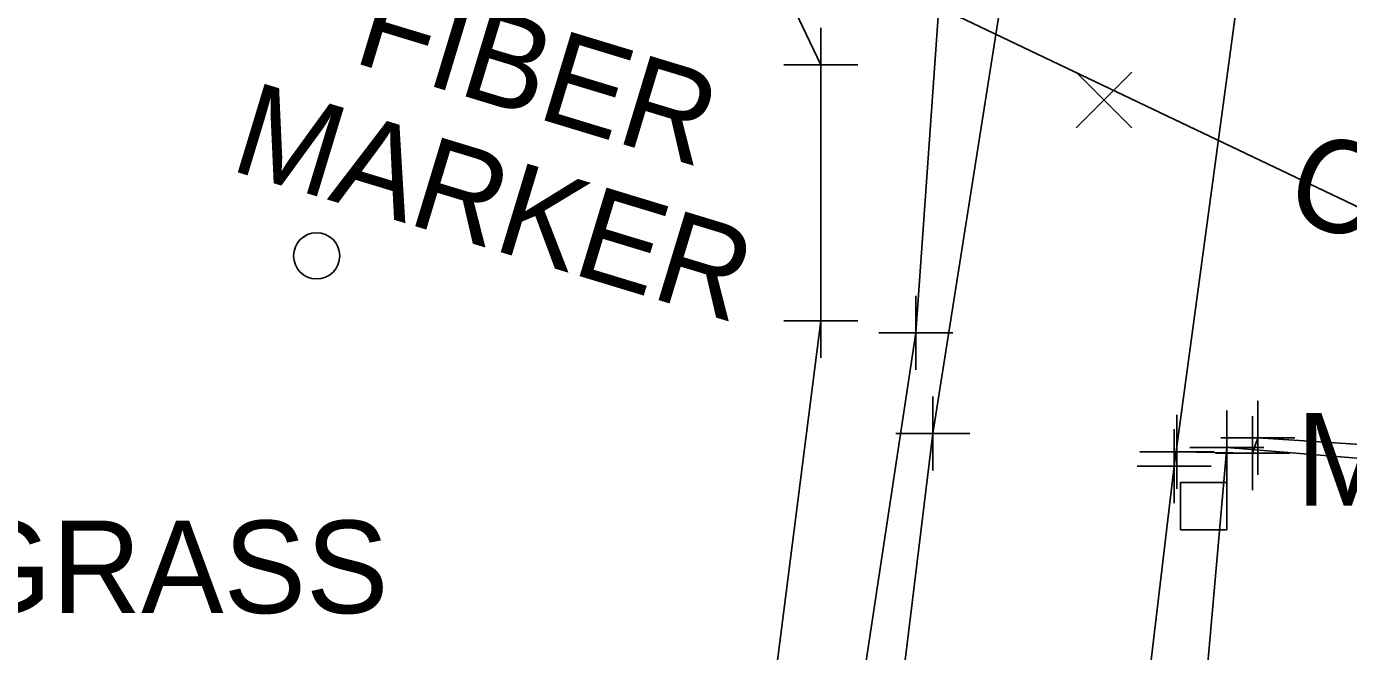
# Model space of a CAD drawing. Extents: x 0 to 1944463, y 0 to 420651.
# Drawn here: x 1942446.1 to 1942517.6, y 417841.3 to 417875.1 of the extents above; entities that cross this region are included whole.
import ezdxf

# ---------------------------------------------------------------- set-up
doc = ezdxf.new("R2010")
doc.units = 0
for name, color, linetype in [('SUR - DTM - Breaklines', 7, 'Continuous'), ('SUR - DTM - Breaklines - Points - Locators', 7, 'Continuous'), ('SUR - DTM - Spot Points - Locators', 7, 'Continuous'), ('SUR - NON-TRAN - Buildings', 7, 'Continuous'), ('SUR - NON-TRAN - Buildings - Points - Locators', 7, 'Continuous'), ('SUR - NON-TRAN - Features', 7, 'Continuous'), ('SUR - PROPERTY - Property Lines', 7, 'Continuous'), ('SUR - TRAN - Features', 7, 'Continuous'), ('SUR - TRAN - Features - Points - Locators', 7, 'Continuous'), ('SUR - TRAN - Features Text', 7, 'Continuous'), ('SUR - TRAN - Roads', 7, 'Continuous'), ('SUR - UTL - Fiber Optic Cable (Underground) Text', 7, 'Continuous'), ('SUR - UTL - Low Wire Crossings', 7, 'Continuous'), ('SUR - UTL - Overhead Wire Crossings', 7, 'Continuous'), ('SUR - VEG - Features Text', 7, 'Continuous')]:
    doc.layers.add(name, color=color, linetype=linetype)

msp = doc.modelspace()

# ---------------------------------------------------------------- linework, layer by layer
at = {"layer": 'SUR - DTM - Breaklines'}
for points in [[(1942474.302, 417799.781), (1942482.593, 417808.097), (1942488.689, 417822.467), (1942494.152, 417858.512), (1942495.478, 417877.156), (1942492.158, 417886.698), (1942474.858, 417894.39), (1942438.729, 417907.858)], [(1942471.44, 417800.968), (1942478.816, 417811.036), (1942484.254, 417821.9), (1942489.02, 417859.171), (1942489.024, 417872.994), (1942484.864, 417881.727), (1942475.352, 417886.418), (1942444.917, 417898.625), (1942434.642, 417903.107), (1942430.896, 417892.452), (1942430.415, 417865.797), (1942426.636, 417855.364)]]:
    msp.add_lwpolyline(points, dxfattribs=at)
at = {"layer": 'SUR - DTM - Breaklines - Points - Locators'}
for p, q in [((1942489.024, 417872.994), (1942489.024, 417874.994)), ((1942489.024, 417872.994), (1942487.024, 417872.994)), ((1942489.024, 417872.994), (1942491.024, 417872.994)), ((1942489.024, 417872.994), (1942489.024, 417870.994)), ((1942489.02, 417859.171), (1942489.02, 417861.171)), ((1942494.152, 417858.512), (1942494.152, 417860.512)), ((1942489.02, 417859.171), (1942487.02, 417859.171)), ((1942489.02, 417859.171), (1942491.02, 417859.171)), ((1942489.02, 417859.171), (1942489.02, 417857.171)), ((1942494.152, 417858.512), (1942492.152, 417858.512)), ((1942494.152, 417858.512), (1942496.152, 417858.512)), ((1942494.152, 417858.512), (1942494.152, 417856.512))]:
    msp.add_line(p, q, dxfattribs=at)
at = {"layer": 'SUR - DTM - Spot Points - Locators'}
msp.add_line((1942461.767, 417862.666), (1942461.767, 417862.666), dxfattribs=at)
msp.add_circle((1942461.756, 417862.677), 1.25, dxfattribs=at)
at = {"layer": 'SUR - NON-TRAN - Buildings'}
msp.add_lwpolyline([(1942539.099, 417850.009), (1942510.981, 417852.328), (1942504.699, 417781.243), (1942533.946, 417778.782), (1942539.15, 417848.98)], close=True, dxfattribs=at)
at = {"layer": 'SUR - NON-TRAN - Buildings - Points - Locators'}
for q in [(1942510.981, 417854.328), (1942508.981, 417852.328), (1942512.981, 417852.328), (1942510.981, 417850.328)]:
    msp.add_line((1942510.981, 417852.328), q, dxfattribs=at)
at = {"layer": 'SUR - NON-TRAN - Features'}
msp.add_line((1942509.72, 417849.176), (1942509.72, 417849.176), dxfattribs=at)
msp.add_lwpolyline([(1942508.47, 417847.876), (1942508.47, 417850.426), (1942510.97, 417850.426), (1942510.97, 417847.876)], close=True, dxfattribs=at)
at = {"layer": 'SUR - PROPERTY - Property Lines'}
for p, q in [((1942495.08, 417853.07), (1942495.08, 417855.07)), ((1942495.08, 417853.07), (1942493.08, 417853.07)), ((1942495.08, 417853.07), (1942497.08, 417853.07)), ((1942495.08, 417853.07), (1942495.08, 417851.07)), ((1942508.124, 417851.308), (1942508.124, 417853.308)), ((1942508.124, 417851.308), (1942506.124, 417851.308)), ((1942508.124, 417851.308), (1942510.124, 417851.308)), ((1942508.124, 417851.308), (1942508.124, 417849.308))]:
    msp.add_line(p, q, dxfattribs=at)
at = {"layer": 'SUR - TRAN - Features'}
msp.add_lwpolyline([(1942565.247, 417861.542), (1942538.832, 417851.155), (1942512.646, 417852.85), (1942512.365, 417852.009), (1942508.279, 417852.084)], dxfattribs=at)
at = {"layer": 'SUR - TRAN - Features - Points - Locators'}
for p, q in [((1942512.646, 417852.85), (1942512.646, 417854.85)), ((1942508.279, 417852.084), (1942508.279, 417854.084)), ((1942512.365, 417852.009), (1942512.365, 417854.009)), ((1942512.646, 417852.85), (1942510.646, 417852.85)), ((1942512.646, 417852.85), (1942514.646, 417852.85)), ((1942512.646, 417852.85), (1942512.646, 417850.85)), ((1942508.279, 417852.084), (1942506.279, 417852.084)), ((1942508.279, 417852.084), (1942510.279, 417852.084)), ((1942508.279, 417852.084), (1942508.279, 417850.084)), ((1942512.365, 417852.009), (1942510.365, 417852.009)), ((1942512.365, 417852.009), (1942514.365, 417852.009)), ((1942512.365, 417852.009), (1942512.365, 417850.009))]:
    msp.add_line(p, q, dxfattribs=at)
at = {"layer": 'SUR - TRAN - Roads'}
for points in [[(1942500.227, 417885.715), (1942495.08, 417853.07), (1942490.671, 417817.072), (1942487.382, 417774.921)], [(1942512.186, 417881.212), (1942508.124, 417851.308), (1942504.029, 417816.844), (1942499.548, 417772.32)]]:
    msp.add_lwpolyline(points, dxfattribs=at)
at = {"layer": 'SUR - UTL - Low Wire Crossings'}
for p, q in [((1942502.829, 417872.601), (1942505.829, 417869.601)), ((1942505.829, 417872.601), (1942502.829, 417869.601)), ((1942504.329, 417871.101), (1942504.329, 417871.101))]:
    msp.add_line(p, q, dxfattribs=at)
at = {"layer": 'SUR - UTL - Overhead Wire Crossings'}
msp.add_lwpolyline([(1942464.637, 417890.792), (1942554.719, 417847.85)], dxfattribs=at)

# ---------------------------------------------------------------- texts
at = {"layer": 'SUR - NON-TRAN - Features'}
msp.add_text('MB', height=5, dxfattribs=at).set_placement((1942514.72, 417849.176))
at = {"layer": 'SUR - TRAN - Features Text'}
msp.add_text('CONC.', height=5, rotation=340.50341, dxfattribs=at).set_placement((1942513.881, 417864.916))
at = {"layer": 'SUR - UTL - Fiber Optic Cable (Underground) Text'}
for s, p in [('FIBER', (1942463.602, 417873.174)), ('MARKER', (1942456.966, 417867.349))]:
    msp.add_text(s, height=5, rotation=343.12173, dxfattribs=at).set_placement(p)
at = {"layer": 'SUR - VEG - Features Text'}
msp.add_text('GRASS', height=5, dxfattribs=at).set_placement((1942442.235, 417843.369))

doc.saveas('drawing.dxf')
